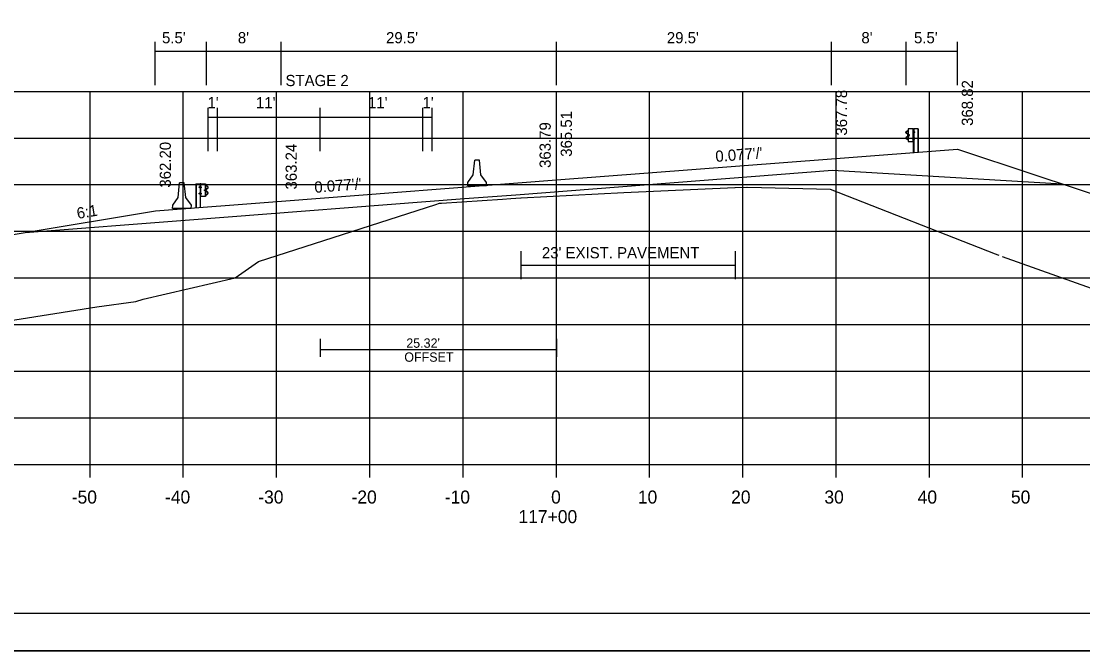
# Model space of a CAD drawing. Extents: x 1374859 to 1376773, y 382242 to 389804.
# Drawn here: x 1376077.2 to 1376191, y 383521.8 to 383589.3 of the extents above; entities that cross this region are included whole.
import ezdxf

# ---------------------------------------------------------------- set-up
doc = ezdxf.new("R2010")
doc.units = 0
for name, color, linetype in [('R_Axis', 7, 'Continuous'), ('R_Axis Annot', 7, 'Continuous'), ('R_Border', 7, 'Continuous'), ('R_Border Notes', 7, 'Continuous'), ('R_Draft', 7, 'Continuous'), ('R_Exist Surface', 7, 'Continuous'), ('R_Fin Surface', 7, 'Continuous'), ('R_Grid', 7, 'Continuous'), ('R_MOT', 7, 'Continuous'), ('R_No Plot', 7, 'Continuous'), ('R_Proposed Road', 7, 'Continuous'), ('R_Xsect Elev', 7, 'Continuous'), ('R_Xsect Slope', 7, 'Continuous')]:
    doc.layers.add(name, color=color, linetype=linetype)

msp = doc.modelspace()

# ---------------------------------------------------------------- linework, layer by layer
at = {"layer": 'R_Axis'}
for p, q in [((1375994.57, 383541.75), (1376274.57, 383541.75)), ((1376084.57, 383540.35), (1376084.57, 383541.75)), ((1376094.57, 383540.35), (1376094.57, 383541.75)), ((1376104.57, 383540.35), (1376104.57, 383541.75)), ((1376114.57, 383540.35), (1376114.57, 383541.75)), ((1376124.57, 383540.35), (1376124.57, 383541.75)), ((1376134.57, 383540.35), (1376134.57, 383541.75)), ((1376144.57, 383540.35), (1376144.57, 383541.75)), ((1376154.57, 383540.35), (1376154.57, 383541.75)), ((1376164.57, 383540.35), (1376164.57, 383541.75)), ((1376174.57, 383540.35), (1376174.57, 383541.75)), ((1376184.57, 383540.35), (1376184.57, 383541.75))]:
    msp.add_line(p, q, dxfattribs=at)
at = {"layer": 'R_Border'}
msp.add_line((1376292.75, 383525.75), (1375976.57, 383525.75), dxfattribs=at)
at = {"layer": 'R_Border Notes'}
for points in [[(1376130.77, 383564.63), (1376130.77, 383561.63)], [(1376153.75, 383564.63), (1376153.75, 383561.63)], [(1376130.77, 383563.13), (1376153.75, 383563.13)]]:
    msp.add_lwpolyline(points, dxfattribs=at)
at = {"layer": 'R_Exist Surface'}
for points in [[(1376074.93, 383557.02), (1376085.29, 383558.64), (1376089.49, 383559.22), (1376090.28, 383559.46), (1376100.14, 383561.76), (1376102.64, 383563.51), (1376121.65, 383569.62), (1376122.04, 383569.76), (1376122.27, 383569.77), (1376128.79, 383570.2), (1376129.7, 383570.26), (1376130.77, 383570.33), (1376130.77, 383570.34), (1376130.8, 383570.34), (1376141.79, 383570.92), (1376153.71, 383571.43), (1376153.75, 383571.43), (1376153.75, 383571.43), (1376154.99, 383571.47), (1376155.04, 383571.47), (1376156.57, 383571.44), (1376163.92, 383571.26), (1376181.63, 383564.34), (1376181.92, 383564.23), (1376182, 383564.19)], [(1376182.38, 383564.04), (1376203.57, 383556.51), (1376216.32, 383555.58), (1376230.46, 383554.66), (1376231.44, 383554.43), (1376237.83, 383551.76), (1376245.42, 383552.07), (1376247.84, 383552.23), (1376256.76, 383554.35), (1376256.98, 383554.43), (1376274.57, 383554.49)]]:
    msp.add_lwpolyline(points, dxfattribs=at)
at = {"layer": 'R_Fin Surface'}
for points in [[(1376005.04, 383556.78), (1376025.94, 383549.82), (1376075.09, 383566.2), (1376077.63, 383566.62), (1376091.59, 383568.95), (1376105.09, 383569.99), (1376134.59, 383572.26), (1376164.09, 383574.53), (1376177.59, 383575.57), (1376185.76, 383572.85), (1376194.09, 383570.07), (1376250.86, 383551.15), (1376260.73, 383554.44)], [(1376077.63, 383566.62), (1376095.23, 383567.98), (1376124.71, 383570.25), (1376130.21, 383570.67), (1376164.18, 383573.29), (1376188.81, 383571.83)]]:
    msp.add_lwpolyline(points, dxfattribs=at)
at = {"layer": 'R_Grid'}
for p, q in [((1375994.57, 383581.75), (1376274.57, 383581.75)), ((1376084.57, 383541.75), (1376084.57, 383581.75)), ((1376094.57, 383541.75), (1376094.57, 383581.75)), ((1376104.57, 383541.75), (1376104.57, 383581.75)), ((1376114.57, 383541.75), (1376114.57, 383581.75)), ((1376124.57, 383541.75), (1376124.57, 383581.75)), ((1376134.57, 383541.75), (1376134.57, 383581.75)), ((1376144.57, 383541.75), (1376144.57, 383581.75)), ((1376154.57, 383541.75), (1376154.57, 383581.75)), ((1376164.57, 383541.75), (1376164.57, 383581.75)), ((1376174.57, 383541.75), (1376174.57, 383581.75)), ((1376184.57, 383541.75), (1376184.57, 383581.75)), ((1375994.57, 383576.75), (1376274.57, 383576.75)), ((1375994.57, 383571.75), (1376274.57, 383571.75)), ((1375994.57, 383566.75), (1376274.57, 383566.75)), ((1375994.57, 383561.75), (1376274.57, 383561.75)), ((1375994.57, 383556.75), (1376274.57, 383556.75)), ((1375994.57, 383551.75), (1376274.57, 383551.75)), ((1375994.57, 383546.75), (1376274.57, 383546.75)), ((1375994.57, 383541.75), (1376274.57, 383541.75))]:
    msp.add_line(p, q, dxfattribs=at)
at = {"layer": 'R_MOT'}
for p, q in [((1376091.57, 383582.43), (1376091.57, 383587.06)), ((1376097.07, 383582.43), (1376097.07, 383587.06)), ((1376105.07, 383582.43), (1376105.07, 383587.06)), ((1376134.57, 383582.43), (1376134.57, 383587.06)), ((1376164.07, 383582.43), (1376164.07, 383587.06)), ((1376172.07, 383582.43), (1376172.07, 383587.06)), ((1376177.57, 383582.43), (1376177.57, 383587.06)), ((1376091.57, 383586.06), (1376177.57, 383586.06)), ((1376097.25, 383575.35), (1376097.25, 383579.99)), ((1376098.25, 383575.35), (1376098.25, 383579.99)), ((1376109.25, 383575.35), (1376109.25, 383579.99)), ((1376120.25, 383575.35), (1376120.25, 383579.99)), ((1376121.25, 383575.35), (1376121.25, 383579.99)), ((1376097.25, 383578.99), (1376121.25, 383578.99)), ((1376125.65, 383572.8), (1376125.82, 383574.38)), ((1376126.07, 383574.38), (1376125.82, 383574.38)), ((1376126.32, 383574.38), (1376126.07, 383574.38)), ((1376126.49, 383572.8), (1376126.32, 383574.38)), ((1376094.01, 383570.38), (1376094.18, 383571.96)), ((1376094.43, 383571.96), (1376094.18, 383571.96)), ((1376094.68, 383571.96), (1376094.43, 383571.96)), ((1376094.85, 383570.38), (1376094.68, 383571.96)), ((1376125.07, 383571.63), (1376125.08, 383571.97)), ((1376125.08, 383571.97), (1376125.65, 383572.8)), ((1376127.08, 383571.97), (1376126.49, 383572.8)), ((1376127.07, 383571.63), (1376127.08, 383571.97)), ((1376127.07, 383571.63), (1376125.07, 383571.63)), ((1376093.43, 383569.21), (1376093.44, 383569.55)), ((1376093.44, 383569.55), (1376094.01, 383570.38)), ((1376095.44, 383569.55), (1376094.85, 383570.38)), ((1376095.43, 383569.21), (1376095.44, 383569.55)), ((1376095.43, 383569.21), (1376093.43, 383569.21)), ((1376109.25, 383555.22), (1376109.25, 383553.29)), ((1376134.57, 383555.22), (1376134.57, 383553.29)), ((1376134.57, 383554.04), (1376109.25, 383554.04))]:
    msp.add_line(p, q, dxfattribs=at)
at = {"layer": 'R_No Plot'}
msp.add_line((1375964.17, 383521.77), (1376297.5, 383521.77), dxfattribs=at)
for points in [[(1375964.16, 383735.1), (1376297.5, 383735.1), (1376297.5, 383521.77), (1375964.16, 383521.77)], [(1376210.49, 383731.21), (1376210.49, 383721.33), (1376246.22, 383721.33), (1376246.22, 383718.41), (1376269.42, 383718.41), (1376269.42, 383694.08), (1376292.75, 383694.08), (1376292.75, 383525.75), (1375976.57, 383525.75), (1375976.57, 383731.21)]]:
    msp.add_lwpolyline(points, close=True, dxfattribs=at)
at = {"layer": 'R_Proposed Road'}
for p, q in [((1376172.06, 383577.43), (1376172.19, 383577.53)), ((1376172.08, 383577.41), (1376172.21, 383577.51)), ((1376172.19, 383577.53), (1376172.31, 383577.59)), ((1376172.21, 383577.51), (1376172.3, 383577.56)), ((1376172.34, 383576.38), (1376172.34, 383577.74)), ((1376172.83, 383577.44), (1376172.78, 383577.44)), ((1376172.78, 383577.44), (1376172.78, 383577.31)), ((1376172.84, 383577.75), (1376172.84, 383577.75)), ((1376172.84, 383577.75), (1376172.91, 383577.74)), ((1376172.87, 383575.23), (1376172.87, 383577.75)), ((1376172.91, 383577.32), (1376172.91, 383577.44)), ((1376172.91, 383577.44), (1376172.95, 383577.44)), ((1376172.91, 383577.41), (1376172.96, 383577.41)), ((1376172.96, 383577.33), (1376172.96, 383577.43)), ((1376173.33, 383577.74), (1376173.33, 383575.23)), ((1376173.36, 383577.74), (1376173.36, 383575.23)), ((1376172.19, 383576.58), (1376172.06, 383576.69)), ((1376172.24, 383577.18), (1376172.07, 383577.28)), ((1376172.25, 383577.2), (1376172.08, 383577.3)), ((1376172.2, 383576.6), (1376172.08, 383576.7)), ((1376172.09, 383576.85), (1376172.24, 383576.94)), ((1376172.1, 383576.83), (1376172.26, 383576.92)), ((1376172.3, 383576.52), (1376172.19, 383576.58)), ((1376172.31, 383576.54), (1376172.2, 383576.6)), ((1376172.27, 383577), (1376172.27, 383577.13)), ((1376172.3, 383577), (1376172.3, 383577.13)), ((1376172.35, 383577), (1376172.35, 383577.12)), ((1376172.35, 383577.12), (1376172.4, 383577.12)), ((1376172.35, 383577.09), (1376172.4, 383577.09)), ((1376172.35, 383577.03), (1376172.39, 383577.03)), ((1376172.35, 383577.03), (1376172.4, 383577.03)), ((1376172.35, 383577), (1376172.4, 383577)), ((1376172.41, 383577.01), (1376172.41, 383577.11)), ((1376172.78, 383577.38), (1376172.84, 383577.38)), ((1376172.83, 383577.31), (1376172.78, 383577.31)), ((1376172.78, 383576.63), (1376172.78, 383576.75)), ((1376172.78, 383576.75), (1376172.83, 383576.75)), ((1376172.78, 383576.69), (1376172.84, 383576.69)), ((1376172.78, 383576.63), (1376172.83, 383576.63)), ((1376172.84, 383576.38), (1376172.87, 383576.38)), ((1376172.91, 383577.35), (1376172.95, 383577.35)), ((1376172.91, 383577.35), (1376172.96, 383577.35)), ((1376172.91, 383577.32), (1376172.96, 383577.32)), ((1376172.92, 383576.63), (1376172.92, 383576.75)), ((1376172.92, 383576.75), (1376172.97, 383576.75)), ((1376172.92, 383576.72), (1376172.97, 383576.72)), ((1376172.92, 383576.66), (1376172.96, 383576.66)), ((1376172.92, 383576.66), (1376172.97, 383576.66)), ((1376172.92, 383576.63), (1376172.97, 383576.63)), ((1376172.97, 383576.64), (1376172.97, 383576.74)), ((1376095.92, 383571.84), (1376095.92, 383569.32)), ((1376095.95, 383571.84), (1376095.95, 383569.32)), ((1376096.44, 383571.84), (1376096.37, 383571.84)), ((1376096.41, 383569.32), (1376096.41, 383571.84)), ((1376096.44, 383571.84), (1376096.44, 383571.84)), ((1376096.94, 383570.47), (1376096.94, 383571.83)), ((1376096.36, 383570.85), (1376096.31, 383570.85)), ((1376096.31, 383570.74), (1376096.31, 383570.83)), ((1376096.36, 383570.82), (1376096.31, 383570.82)), ((1376096.36, 383570.75), (1376096.31, 383570.75)), ((1376096.36, 383570.72), (1376096.31, 383570.72)), ((1376096.37, 383571.54), (1376096.32, 383571.54)), ((1376096.32, 383571.43), (1376096.32, 383571.52)), ((1376096.37, 383571.51), (1376096.32, 383571.51)), ((1376096.37, 383571.44), (1376096.32, 383571.44)), ((1376096.37, 383571.41), (1376096.32, 383571.41)), ((1376096.36, 383570.75), (1376096.32, 383570.75)), ((1376096.37, 383571.44), (1376096.33, 383571.44)), ((1376096.36, 383570.72), (1376096.36, 383570.85)), ((1376096.37, 383571.41), (1376096.37, 383571.54)), ((1376096.5, 383571.47), (1376096.44, 383571.47)), ((1376096.5, 383570.78), (1376096.44, 383570.78)), ((1376096.45, 383571.53), (1376096.5, 383571.53)), ((1376096.45, 383571.41), (1376096.5, 383571.41)), ((1376096.5, 383570.85), (1376096.45, 383570.85)), ((1376096.5, 383570.72), (1376096.45, 383570.72)), ((1376096.5, 383571.53), (1376096.5, 383571.41)), ((1376096.5, 383570.72), (1376096.5, 383570.85)), ((1376096.87, 383571.1), (1376096.87, 383571.2)), ((1376096.93, 383571.21), (1376096.88, 383571.21)), ((1376096.93, 383571.18), (1376096.88, 383571.18)), ((1376096.93, 383571.12), (1376096.88, 383571.12)), ((1376096.93, 383571.12), (1376096.88, 383571.12)), ((1376096.93, 383571.09), (1376096.88, 383571.09)), ((1376096.93, 383571.09), (1376096.93, 383571.21)), ((1376097.08, 383571.62), (1376096.97, 383571.68)), ((1376096.97, 383570.63), (1376097.08, 383570.69)), ((1376097.07, 383571.61), (1376096.98, 383571.66)), ((1376096.98, 383571.09), (1376096.98, 383571.22)), ((1376096.98, 383570.61), (1376097.09, 383570.67)), ((1376097, 383571.09), (1376097.01, 383571.22)), ((1376097.18, 383570.92), (1376097.02, 383571.02)), ((1376097.03, 383571.29), (1376097.2, 383571.4)), ((1376097.19, 383570.94), (1376097.03, 383571.04)), ((1376097.04, 383571.27), (1376097.21, 383571.37)), ((1376097.2, 383571.5), (1376097.07, 383571.61)), ((1376097.21, 383571.52), (1376097.08, 383571.62)), ((1376097.08, 383570.69), (1376097.2, 383570.8)), ((1376097.09, 383570.67), (1376097.22, 383570.78)), ((1376096.44, 383570.47), (1376096.41, 383570.47))]:
    msp.add_line(p, q, dxfattribs=at)
for points in [[(1376172.31, 383577.75), (1376172.31, 383576.38), (1376172.84, 383576.38), (1376172.84, 383577.75)], [(1376172.78, 383577.44), (1376172.78, 383577.31), (1376172.84, 383577.31), (1376172.84, 383577.44)], [(1376172.91, 383577.46), (1376172.91, 383577.3), (1376172.9, 383577.3), (1376172.9, 383577.46)], [(1376172.96, 383577.41), (1376172.96, 383577.35), (1376172.99, 383577.35), (1376172.99, 383577.41)], [(1376172.35, 383577.14), (1376172.35, 383576.97), (1376172.34, 383576.97), (1376172.34, 383577.14)], [(1376172.41, 383577.09), (1376172.41, 383577.03), (1376172.43, 383577.03), (1376172.43, 383577.09)], [(1376172.78, 383576.75), (1376172.78, 383576.63), (1376172.84, 383576.63), (1376172.84, 383576.75)], [(1376172.92, 383576.77), (1376172.92, 383576.61), (1376172.91, 383576.61), (1376172.91, 383576.77)], [(1376172.97, 383576.72), (1376172.97, 383576.66), (1376173, 383576.66), (1376173, 383576.72)], [(1376096.97, 383571.84), (1376096.97, 383570.47), (1376096.44, 383570.47), (1376096.44, 383571.84)], [(1376096.3, 383570.82), (1376096.3, 383570.75), (1376096.28, 383570.75), (1376096.28, 383570.82)], [(1376096.31, 383571.5), (1376096.31, 383571.44), (1376096.29, 383571.44), (1376096.29, 383571.5)], [(1376096.36, 383570.87), (1376096.36, 383570.7), (1376096.37, 383570.7), (1376096.37, 383570.87)], [(1376096.37, 383571.56), (1376096.37, 383571.39), (1376096.38, 383571.39), (1376096.38, 383571.56)], [(1376096.5, 383571.53), (1376096.5, 383571.41), (1376096.44, 383571.41), (1376096.44, 383571.53)], [(1376096.5, 383570.85), (1376096.5, 383570.72), (1376096.44, 383570.72), (1376096.44, 383570.85)], [(1376096.87, 383571.18), (1376096.87, 383571.12), (1376096.85, 383571.12), (1376096.85, 383571.18)], [(1376096.93, 383571.23), (1376096.93, 383571.07), (1376096.94, 383571.07), (1376096.94, 383571.23)]]:
    msp.add_lwpolyline(points, close=True, dxfattribs=at)
for points in [[(1376173.36, 383577.74), (1376172.91, 383577.74), (1376172.91, 383575.23)], [(1376095.92, 383571.84), (1376096.37, 383571.84), (1376096.37, 383569.32)]]:
    msp.add_lwpolyline(points, dxfattribs=at)
for centre, radius, start, end in [((1376172.11, 383577.36), 0.0856, 122.0217, 240.7501), ((1376172.11, 383577.36), 0.062, 122.0217, 240.7501), ((1376172.94, 383577.43), 0.022, 317.7756, 45.4255), ((1376172.87, 383577.38), 0.0922, 339.7423, 20.2577), ((1376172.15, 383576.75), 0.109, 120.88, 214.7816), ((1376172.15, 383576.75), 0.0854, 120.88, 214.7816), ((1376172.28, 383577.06), 0.0453, 93.9303, 257.0446), ((1376172.21, 383577.12), 0.0622, 4.9556, 61.894), ((1376172.21, 383577.12), 0.0865, 4.9556, 61.894), ((1376172.23, 383576.99), 0.0462, 293.1464, 8.2196), ((1376172.23, 383576.99), 0.0703, 293.1464, 8.2196), ((1376172.38, 383577.11), 0.022, 317.7756, 45.4255), ((1376172.31, 383577.06), 0.0922, 339.7423, 20.2577), ((1376172.38, 383577.01), 0.025, 323.3766, 39.0666), ((1376172.94, 383577.33), 0.025, 323.3766, 39.0666), ((1376172.95, 383576.74), 0.022, 317.7756, 45.4255), ((1376172.88, 383576.69), 0.0922, 339.7423, 20.2577), ((1376172.95, 383576.64), 0.025, 323.3766, 39.0666), ((1376096.33, 383570.83), 0.022, 134.5745, 222.2244), ((1376096.4, 383570.78), 0.0922, 159.7423, 200.2577), ((1376096.33, 383570.74), 0.025, 140.9334, 216.6234), ((1376096.34, 383571.52), 0.022, 134.5745, 222.2244), ((1376096.41, 383571.47), 0.0922, 159.7423, 200.2577), ((1376096.34, 383571.43), 0.025, 140.9334, 216.6234), ((1376096.89, 383571.2), 0.022, 134.5745, 222.2244), ((1376096.96, 383571.15), 0.0922, 159.7423, 200.2577), ((1376096.9, 383571.1), 0.025, 140.9334, 216.6234), ((1376097.07, 383571.21), 0.0865, 118.106, 175.0444), ((1376097.05, 383571.08), 0.0703, 171.7804, 246.8536), ((1376097.07, 383571.21), 0.0622, 118.106, 175.0444), ((1376097, 383571.15), 0.0453, 282.9554, 86.0697), ((1376097.05, 383571.08), 0.0462, 171.7804, 246.8536), ((1376097.13, 383570.85), 0.0854, 325.2184, 59.12), ((1376097.13, 383570.85), 0.109, 325.2184, 59.12), ((1376097.17, 383571.45), 0.062, 299.2499, 57.9783), ((1376097.17, 383571.45), 0.0856, 299.2499, 57.9783)]:
    msp.add_arc(centre, radius, start, end, dxfattribs=at)

# ---------------------------------------------------------------- texts
at = {"layer": 'R_Axis Annot'}
for s, p in [('-50', (1376082.61, 383537.55)), ('-40', (1376092.61, 383537.55)), ('-30', (1376102.61, 383537.55)), ('-20', (1376112.61, 383537.55)), ('-10', (1376122.61, 383537.55)), ('0', (1376134.01, 383537.55)), ('10', (1376143.31, 383537.55)), ('20', (1376153.31, 383537.55)), ('30', (1376163.31, 383537.55)), ('40', (1376173.31, 383537.55)), ('50', (1376183.31, 383537.55)), ('117+00', (1376130.51, 383535.45))]:
    msp.add_text(s, height=1.4, dxfattribs=at).set_placement(p)
at = {"layer": 'R_Border Notes'}
msp.add_text("23' EXIST. PAVEMENT", height=1.2, rotation=0, dxfattribs=at).set_placement((1376133.02, 383563.85))
at = {"layer": 'R_Draft'}
for s, p in [("25.32'", (1376118.48, 383554.26)), ('OFFSET', (1376118.27, 383552.76))]:
    msp.add_text(s, height=1, dxfattribs=at).set_placement(p)
at = {"layer": 'R_MOT'}
for s, p in [("5.5'", (1376092.29, 383586.91)), ("8'", (1376100.42, 383586.91)), ("29.5'", (1376116.31, 383586.91)), ("29.5'", (1376146.42, 383586.91)), ("8'", (1376167.28, 383586.91)), ("5.5'", (1376172.92, 383586.91)), ("1'", (1376097.16, 383579.95)), ("11'", (1376102.37, 383579.95)), ("11'", (1376114.38, 383579.95)), ("1'", (1376120.22, 383579.95))]:
    msp.add_text(s, height=1.2, dxfattribs=at).set_placement(p)
msp.add_text('STAGE 2', height=1.2, rotation=0, dxfattribs=at).set_placement((1376105.53, 383582.32))
at = {"layer": 'R_Xsect Elev'}
for s, p in [('368.82', (1376179.24, 383578.05)), ('367.78', (1376165.74, 383577.01)), ('365.51', (1376136.24, 383574.74)), ('363.79', (1376133.97, 383573.54)), ('362.20', (1376093.24, 383571.43)), ('363.24', (1376106.74, 383571.23))]:
    msp.add_text(s, height=1.2, rotation=90, dxfattribs=at).set_placement(p)
at = {"layer": 'R_Xsect Slope'}
for s, rotation, p in [("0.077'/'", 4.4031, (1376151.67, 383574.18)), ("0.077'/'", 4.4031, (1376108.67, 383570.87)), ('6:1', 9.4642, (1376083.25, 383568.07))]:
    msp.add_text(s, height=1.2, rotation=rotation, dxfattribs=at).set_placement(p)

doc.saveas('drawing.dxf')
